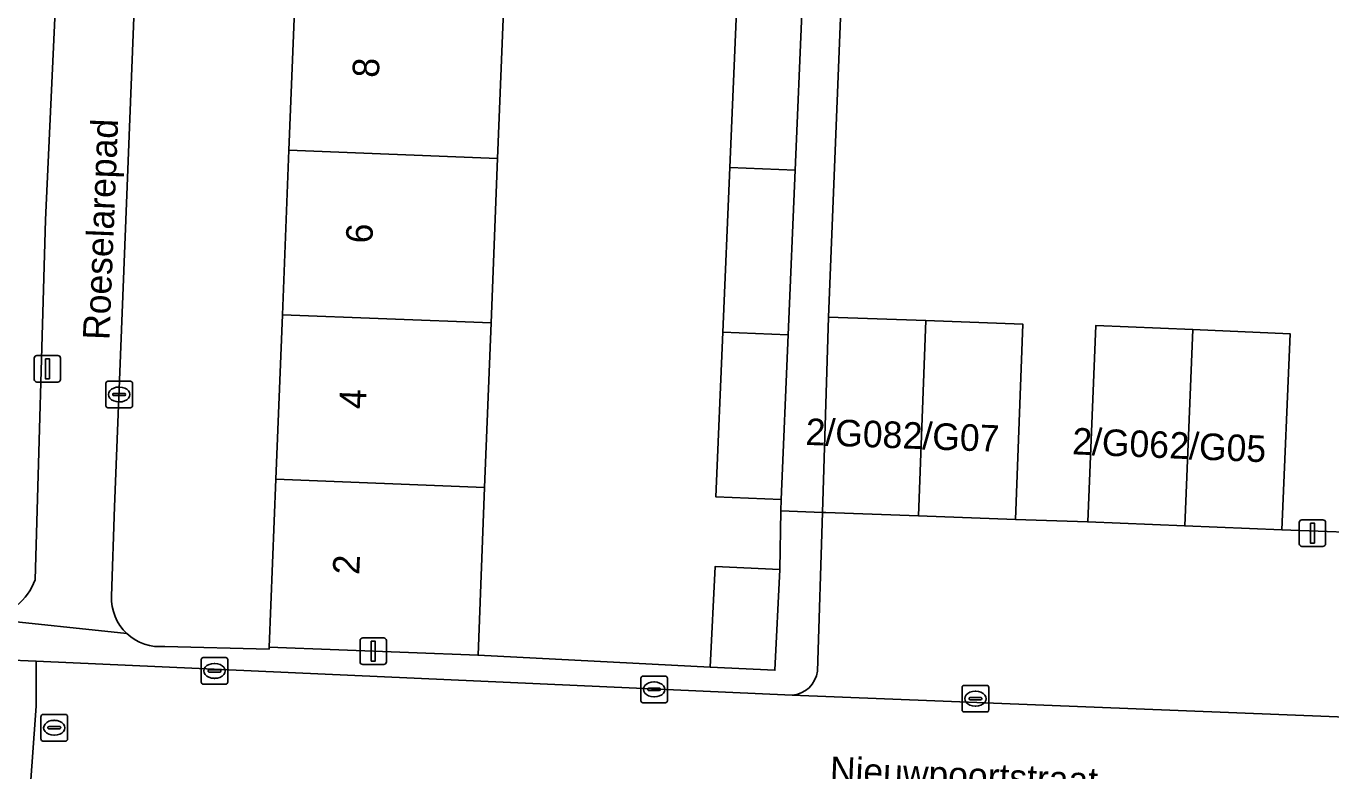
# Model space of a CAD drawing. Extents: x 160732 to 162107, y 387428 to 388479.
# Drawn here: x 161156.38 to 161205.54, y 387527.39 to 387555.43 of the extents above; entities that cross this region are included whole.
import ezdxf

# ---------------------------------------------------------------- set-up
doc = ezdxf.new("R2010")
doc.units = 0
for name, color, linetype in [('IMGEO_Erf', 7, 'Continuous'), ('IMGEO_Kolk', 7, 'Continuous'), ('IMGEO_Lichtmast', 7, 'Continuous'), ('IMGEO_Muur', 7, 'Continuous'), ('IMGEO_Openbare_ruimte_label', 7, 'Continuous'), ('IMGEO_Pand', 7, 'Continuous'), ('IMGEO_Pand_nummerreeks', 7, 'Continuous'), ('IMGEO_Parkeervlak_open', 7, 'Continuous'), ('IMGEO_Rijbaan_lokaal_open', 7, 'Continuous'), ('IMGEO_Rioolput', 7, 'Continuous'), ('IMGEO_Voetpad_open', 7, 'Continuous')]:
    doc.layers.add(name, color=color, linetype=linetype)

msp = doc.modelspace()

# ---------------------------------------------------------------- linework, layer by layer
at = {"layer": 'IMGEO_Erf'}
for points in [[(161156.715, 387534.59), (161157.113, 387548.142), (161158.354, 387575.006)], [(161161.189, 387574.824), (161159.709, 387537.335), (161159.601, 387533.972)], [(161205.924, 387560.017), (161199.746, 387560.266), (161199.575, 387556.024), (161193.395, 387556.274), (161193.566, 387560.516), (161187.266, 387560.77), (161186.614, 387544.478), (161190.269, 387544.344), (161193.924, 387544.211), (161193.655, 387536.856), (161196.373, 387536.766), (161196.679, 387544.156), (161200.34, 387544.004), (161203.998, 387543.853), (161203.692, 387536.462), (161206.427, 387536.369)], [(161161.61, 387532.081), (161165.535, 387531.976), (161165.538, 387532.053), (161165.788, 387538.37), (161166.032, 387544.565), (161166.277, 387550.76), (161166.522, 387556.956)], [(161174.387, 387556.646), (161174.142, 387550.45), (161173.897, 387544.255), (161173.653, 387538.06), (161173.403, 387531.743), (161182.155, 387531.299), (161182.34, 387535.088), (161184.775, 387534.97), (161184.818, 387537.186), (161184.826, 387537.612), (161182.362, 387537.716), (161182.624, 387543.911), (161182.887, 387550.105), (161183.15, 387556.301)]]:
    msp.add_lwpolyline(points, dxfattribs=at)
for centre, radius, start, end in [((161154.582, 387535.364), 2.27, 278.551, 340.0486), ((161161.408, 387533.882), 1.81, 177.1382, 226.7727), ((161161.413, 387533.887), 1.817, 226.7839, 276.2269)]:
    msp.add_arc(centre, radius, start, end, dxfattribs=at)
at = {"layer": 'IMGEO_Kolk'}
for p, q in [((161159.385, 387541.137), (161159.385, 387541.989)), ((161159.46, 387542.063), (161160.312, 387542.063)), ((161160.386, 387541.989), (161160.386, 387541.137)), ((161159.644, 387541.557), (161159.644, 387541.569)), ((161160.082, 387541.52), (161159.684, 387541.52)), ((161159.687, 387541.606), (161160.085, 387541.606)), ((161159.873, 387541.843), (161159.898, 387541.843)), ((161160.128, 387541.569), (161160.128, 387541.557)), ((161160.312, 387541.063), (161159.46, 387541.063)), ((161159.896, 387541.283), (161159.871, 387541.283)), ((161163.051, 387531.656), (161163.903, 387531.656)), ((161162.976, 387530.73), (161162.976, 387531.582)), ((161163.235, 387531.15), (161163.235, 387531.162)), ((161163.278, 387531.199), (161163.676, 387531.199)), ((161163.464, 387531.436), (161163.489, 387531.436)), ((161163.719, 387531.162), (161163.719, 387531.15)), ((161163.977, 387531.582), (161163.977, 387530.73)), ((161163.903, 387530.656), (161163.051, 387530.656)), ((161163.673, 387531.113), (161163.275, 387531.113)), ((161163.487, 387530.876), (161163.462, 387530.876)), ((161179.538, 387530.033), (161179.538, 387530.885)), ((161179.613, 387530.959), (161180.465, 387530.959)), ((161180.026, 387530.739), (161180.051, 387530.739)), ((161180.539, 387530.885), (161180.539, 387530.033)), ((161179.797, 387530.453), (161179.797, 387530.465)), ((161180.235, 387530.416), (161179.837, 387530.416)), ((161179.84, 387530.502), (161180.238, 387530.502)), ((161180.049, 387530.179), (161180.024, 387530.179)), ((161180.281, 387530.465), (161180.281, 387530.453)), ((161191.643, 387529.684), (161191.643, 387530.536)), ((161191.718, 387530.61), (161192.57, 387530.61)), ((161192.131, 387530.39), (161192.156, 387530.39)), ((161192.644, 387530.536), (161192.644, 387529.684)), ((161180.465, 387529.959), (161179.613, 387529.959)), ((161191.902, 387530.104), (161191.902, 387530.116)), ((161192.34, 387530.067), (161191.942, 387530.067)), ((161191.945, 387530.153), (161192.343, 387530.153)), ((161192.154, 387529.83), (161192.129, 387529.83)), ((161192.386, 387530.116), (161192.386, 387530.104)), ((161192.57, 387529.61), (161191.718, 387529.61))]:
    msp.add_line(p, q, dxfattribs=at)
for points in [[(161159.385, 387541.137), (161159.385, 387541.989)], [(161159.46, 387542.063), (161160.312, 387542.063)], [(161160.386, 387541.989), (161160.386, 387541.137)], [(161160.312, 387541.063), (161159.46, 387541.063)], [(161163.051, 387531.656), (161163.903, 387531.656)], [(161162.976, 387530.73), (161162.976, 387531.582)], [(161163.977, 387531.582), (161163.977, 387530.73)], [(161163.903, 387530.656), (161163.051, 387530.656)], [(161179.538, 387530.033), (161179.538, 387530.885)], [(161179.613, 387530.959), (161180.465, 387530.959)], [(161180.539, 387530.885), (161180.539, 387530.033)], [(161191.643, 387529.684), (161191.643, 387530.536)], [(161191.718, 387530.61), (161192.57, 387530.61)], [(161192.644, 387530.536), (161192.644, 387529.684)], [(161180.465, 387529.959), (161179.613, 387529.959)], [(161192.57, 387529.61), (161191.718, 387529.61)]]:
    msp.add_lwpolyline(points, dxfattribs=at)
for centre, radius, start, end in [((161159.462, 387541.987), 0.0765, 91.552, 178.448), ((161159.462, 387541.987), 0.0765, 91.552, 178.448), ((161160.31, 387541.987), 0.0765, 1.552, 88.448), ((161160.31, 387541.987), 0.0765, 1.552, 88.448), ((161159.684, 387541.566), 0.0403, 85.8775, 175.7526), ((161159.681, 387541.556), 0.0366, 178.938, 274.7102), ((161160.085, 387541.563), 0.043, 264.8664, 352.4533), ((161160.089, 387541.568), 0.0386, 1.7309, 96.639), ((161159.462, 387541.139), 0.0765, 181.552, 268.448), ((161159.462, 387541.139), 0.0765, 181.552, 268.448), ((161160.31, 387541.139), 0.0765, 271.552, 358.448), ((161160.31, 387541.139), 0.0765, 271.552, 358.448), ((161163.053, 387531.58), 0.0765, 91.552, 178.448), ((161163.053, 387531.58), 0.0765, 91.552, 178.448), ((161163.901, 387531.58), 0.0765, 1.552, 88.448), ((161163.901, 387531.58), 0.0765, 1.552, 88.448), ((161163.275, 387531.159), 0.0403, 85.8775, 175.7526), ((161163.272, 387531.149), 0.0366, 178.938, 274.7102), ((161163.676, 387531.156), 0.043, 264.8664, 352.4533), ((161163.68, 387531.161), 0.0386, 1.7309, 96.639), ((161163.053, 387530.732), 0.0765, 181.552, 268.448), ((161163.053, 387530.732), 0.0765, 181.552, 268.448), ((161163.901, 387530.732), 0.0765, 271.552, 358.448), ((161163.901, 387530.732), 0.0765, 271.552, 358.448), ((161179.615, 387530.883), 0.0765, 91.552, 178.448), ((161179.615, 387530.883), 0.0765, 91.552, 178.448), ((161180.463, 387530.883), 0.0765, 1.552, 88.448), ((161180.463, 387530.883), 0.0765, 1.552, 88.448), ((161179.837, 387530.462), 0.0403, 85.8775, 175.7526), ((161179.834, 387530.452), 0.0366, 178.938, 274.7102), ((161180.238, 387530.459), 0.043, 264.8664, 352.4533), ((161180.242, 387530.464), 0.0386, 1.7309, 96.639), ((161191.72, 387530.534), 0.0765, 91.552, 178.448), ((161191.72, 387530.534), 0.0765, 91.552, 178.448), ((161192.568, 387530.534), 0.0765, 1.552, 88.448), ((161192.568, 387530.534), 0.0765, 1.552, 88.448), ((161179.615, 387530.035), 0.0765, 181.552, 268.448), ((161179.615, 387530.035), 0.0765, 181.552, 268.448), ((161180.463, 387530.035), 0.0765, 271.552, 358.448), ((161180.463, 387530.035), 0.0765, 271.552, 358.448), ((161191.72, 387529.686), 0.0765, 181.552, 268.448), ((161191.72, 387529.686), 0.0765, 181.552, 268.448), ((161191.942, 387530.113), 0.0403, 85.8775, 175.7526), ((161191.939, 387530.103), 0.0366, 178.938, 274.7102), ((161192.343, 387530.11), 0.043, 264.8664, 352.4533), ((161192.347, 387530.115), 0.0386, 1.7309, 96.639), ((161192.568, 387529.686), 0.0765, 271.552, 358.448), ((161192.568, 387529.686), 0.0765, 271.552, 358.448)]:
    msp.add_arc(centre, radius, start, end, dxfattribs=at)
for centre, major_axis, ratio, start_param, end_param in [((161159.872, 387541.563), (-0.387, 0.002), 0.722429, 4.712389, 7.853982), ((161159.897, 387541.563), (-0.39, 0.002), 0.717154, 1.570796, 4.712389), ((161163.463, 387531.156), (-0.387, 0.002), 0.722429, 4.712389, 7.853982), ((161163.488, 387531.156), (-0.39, 0.002), 0.717154, 1.570796, 4.712389), ((161180.025, 387530.459), (-0.387, 0.002), 0.722429, 4.712389, 7.853982), ((161180.05, 387530.459), (-0.39, 0.002), 0.717154, 1.570796, 4.712389), ((161192.13, 387530.11), (-0.387, 0.002), 0.722429, 4.712389, 7.853982), ((161192.155, 387530.11), (-0.39, 0.002), 0.717154, 1.570796, 4.712389)]:
    msp.add_ellipse(centre, major_axis=major_axis, ratio=ratio, start_param=start_param, end_param=end_param, dxfattribs=at)
at = {"layer": 'IMGEO_Lichtmast'}
for p, q in [((161156.785, 387543.032), (161157.575, 387543.032)), ((161157.575, 387543.032), (161156.785, 387543.032)), ((161156.685, 387542.132), (161156.685, 387542.932)), ((161156.685, 387542.932), (161156.685, 387542.132)), ((161157.675, 387542.932), (161157.675, 387542.132)), ((161157.675, 387542.132), (161157.675, 387542.932)), ((161157.575, 387542.032), (161156.785, 387542.032)), ((161156.785, 387542.032), (161157.575, 387542.032)), ((161204.345, 387535.945), (161204.345, 387536.745)), ((161204.345, 387536.745), (161204.345, 387535.945)), ((161204.445, 387536.845), (161205.235, 387536.845)), ((161205.235, 387536.845), (161204.445, 387536.845)), ((161205.335, 387536.745), (161205.335, 387535.945)), ((161205.335, 387535.945), (161205.335, 387536.745)), ((161205.235, 387535.845), (161204.445, 387535.845)), ((161204.445, 387535.845), (161205.235, 387535.845)), ((161168.96, 387531.499), (161168.96, 387532.299)), ((161168.96, 387532.299), (161168.96, 387531.499)), ((161169.06, 387532.399), (161169.85, 387532.399)), ((161169.85, 387532.399), (161169.06, 387532.399)), ((161169.95, 387532.299), (161169.95, 387531.499)), ((161169.95, 387531.499), (161169.95, 387532.299)), ((161169.85, 387531.399), (161169.06, 387531.399)), ((161169.06, 387531.399), (161169.85, 387531.399))]:
    msp.add_line(p, q, dxfattribs=at)
for points in [[(161157.105, 387542.907), (161157.255, 387542.907), (161157.255, 387542.157), (161157.105, 387542.157), (161157.105, 387542.907)], [(161204.765, 387536.72), (161204.915, 387536.72), (161204.915, 387535.97), (161204.765, 387535.97), (161204.765, 387536.72)], [(161169.38, 387532.274), (161169.53, 387532.274), (161169.53, 387531.524), (161169.38, 387531.524), (161169.38, 387532.274)]]:
    msp.add_lwpolyline(points, dxfattribs=at)
for centre, start, end in [((161156.785, 387542.932), 90, 180), ((161156.785, 387542.932), 90, 180), ((161157.575, 387542.932), 0, 90), ((161157.575, 387542.932), 360, 90), ((161156.785, 387542.132), 180, 270), ((161156.785, 387542.132), 180, 270), ((161157.575, 387542.132), 270, 0), ((161157.575, 387542.132), 270, 0), ((161204.445, 387536.745), 90, 180), ((161204.445, 387536.745), 90, 180), ((161205.235, 387536.745), 0, 90), ((161205.235, 387536.745), 360, 90), ((161204.445, 387535.945), 180, 270), ((161204.445, 387535.945), 180, 270), ((161205.235, 387535.945), 270, 0), ((161205.235, 387535.945), 270, 0), ((161169.06, 387532.299), 90, 180), ((161169.06, 387532.299), 90, 180), ((161169.85, 387532.299), 0, 90), ((161169.85, 387532.299), 360, 90), ((161169.06, 387531.499), 180, 270), ((161169.06, 387531.499), 180, 270), ((161169.85, 387531.499), 270, 0), ((161169.85, 387531.499), 270, 0)]:
    msp.add_arc(centre, 0.1, start, end, dxfattribs=at)
at = {"layer": 'IMGEO_Muur'}
msp.add_lwpolyline([(161173.403, 387531.743), (161182.155, 387531.299)], dxfattribs=at)
at = {"layer": 'IMGEO_Pand'}
for points in [[(161166.522, 387556.956), (161166.277, 387550.76), (161174.142, 387550.45), (161174.387, 387556.646)], [(161185.614, 387556.203), (161183.15, 387556.301), (161182.887, 387550.105), (161185.352, 387550.008)], [(161173.897, 387544.255), (161174.142, 387550.45), (161166.277, 387550.76), (161166.032, 387544.565)], [(161185.352, 387550.008), (161182.887, 387550.105), (161182.624, 387543.911), (161185.089, 387543.814)], [(161166.032, 387544.565), (161165.788, 387538.37), (161173.653, 387538.06), (161173.897, 387544.255)], [(161186.508, 387537.117), (161190, 387536.989), (161190.269, 387544.344), (161186.614, 387544.478), (161186.385, 387537.122)], [(161193.655, 387536.856), (161193.924, 387544.211), (161190.269, 387544.344), (161190, 387536.989)], [(161200.032, 387536.614), (161200.34, 387544.004), (161196.679, 387544.156), (161196.373, 387536.766)], [(161203.692, 387536.462), (161203.998, 387543.853), (161200.34, 387544.004), (161200.032, 387536.614)], [(161185.089, 387543.814), (161182.624, 387543.911), (161182.362, 387537.716), (161184.826, 387537.612)], [(161173.403, 387531.743), (161173.653, 387538.06), (161165.788, 387538.37), (161165.538, 387532.053)], [(161184.591, 387531.181), (161184.775, 387534.97), (161182.34, 387535.088), (161182.155, 387531.299)]]:
    msp.add_lwpolyline(points, close=True, dxfattribs=at)
at = {"layer": 'IMGEO_Parkeervlak_open'}
for points in [[(161223.236, 387529.657), (161223.347, 387529.985), (161223.523, 387535.736), (161220.063, 387535.856), (161216.463, 387535.98), (161213.737, 387536.067), (161210.079, 387536.218), (161206.427, 387536.369), (161203.692, 387536.462), (161200.032, 387536.614), (161196.373, 387536.766), (161193.655, 387536.856), (161190, 387536.989), (161186.508, 387537.117), (161186.385, 387537.122), (161186.19, 387531.148)], [(161185.233, 387530.24), (161224.12, 387528.698)]]:
    msp.add_lwpolyline(points, dxfattribs=at)
msp.add_arc((161185.158, 387531.277), 1.04, 274.1375, 352.8525, dxfattribs=at)
at = {"layer": 'IMGEO_Rijbaan_lokaal_open'}
msp.add_lwpolyline([(161150.551, 387526.662), (161156.521, 387526.524), (161156.756, 387529.831), (161156.757, 387531.52), (161150.782, 387531.772)], close=True, dxfattribs=at)
msp.add_lwpolyline([(161250.799, 387527.613), (161224.12, 387528.698), (161185.233, 387530.24), (161156.757, 387531.52), (161156.756, 387529.831), (161156.521, 387526.524), (161157.05, 387526.491), (161182.151, 387525.401), (161185.563, 387525.285), (161228.389, 387523.514), (161228.548, 387523.509), (161244.661, 387522.856), (161247.682, 387522.742), (161252.229, 387522.571)], dxfattribs=at)
at = {"layer": 'IMGEO_Rioolput'}
for p, q in [((161156.939, 387528.589), (161156.939, 387529.441)), ((161157.014, 387529.515), (161157.866, 387529.515)), ((161157.427, 387529.295), (161157.452, 387529.295)), ((161157.94, 387529.441), (161157.94, 387528.589)), ((161157.198, 387529.009), (161157.198, 387529.021)), ((161157.636, 387528.972), (161157.238, 387528.972)), ((161157.241, 387529.058), (161157.639, 387529.058)), ((161157.45, 387528.735), (161157.425, 387528.735)), ((161157.682, 387529.021), (161157.682, 387529.009)), ((161157.866, 387528.515), (161157.014, 387528.515))]:
    msp.add_line(p, q, dxfattribs=at)
for points in [[(161156.939, 387528.589), (161156.939, 387529.441)], [(161157.014, 387529.515), (161157.866, 387529.515)], [(161157.94, 387529.441), (161157.94, 387528.589)], [(161157.866, 387528.515), (161157.014, 387528.515)]]:
    msp.add_lwpolyline(points, dxfattribs=at)
for centre, radius, start, end in [((161157.016, 387529.439), 0.0765, 91.552, 178.448), ((161157.016, 387529.439), 0.0765, 91.552, 178.448), ((161157.864, 387529.439), 0.0765, 1.552, 88.448), ((161157.864, 387529.439), 0.0765, 1.552, 88.448), ((161157.238, 387529.018), 0.0403, 85.8775, 175.7526), ((161157.235, 387529.008), 0.0366, 178.938, 274.7102), ((161157.639, 387529.015), 0.043, 264.8664, 352.4533), ((161157.643, 387529.02), 0.0386, 1.7309, 96.639), ((161157.016, 387528.591), 0.0765, 181.552, 268.448), ((161157.016, 387528.591), 0.0765, 181.552, 268.448), ((161157.864, 387528.591), 0.0765, 271.552, 358.448), ((161157.864, 387528.591), 0.0765, 271.552, 358.448)]:
    msp.add_arc(centre, radius, start, end, dxfattribs=at)
for centre, major_axis, ratio, start_param, end_param in [((161157.426, 387529.015), (-0.387, 0.002), 0.722429, 4.712389, 7.853982), ((161157.451, 387529.015), (-0.39, 0.002), 0.717154, 1.570796, 4.712389)]:
    msp.add_ellipse(centre, major_axis=major_axis, ratio=ratio, start_param=start_param, end_param=end_param, dxfattribs=at)
at = {"layer": 'IMGEO_Voetpad_open'}
for points in [[(161160.169, 387532.563), (161154.919, 387533.12), (161148.873, 387533.469), (161136.191, 387533.922), (161136.177, 387533.542), (161131.639, 387533.72), (161118.993, 387534.338), (161116.748, 387536.89), (161118.175, 387572.62), (161118.779, 387585.972)], [(161158.354, 387575.006), (161157.113, 387548.142), (161156.715, 387534.59)], [(161159.601, 387533.972), (161159.709, 387537.335), (161161.189, 387574.824)], [(161186.19, 387531.148), (161186.385, 387537.122), (161184.818, 387537.186), (161184.775, 387534.97), (161184.591, 387531.181), (161182.155, 387531.299), (161173.403, 387531.743), (161165.538, 387532.053), (161165.535, 387531.976), (161161.61, 387532.081)], [(161154.919, 387533.12), (161160.169, 387532.563)], [(161118.93, 387533.102), (161150.782, 387531.772), (161156.757, 387531.52), (161185.233, 387530.24)]]:
    msp.add_lwpolyline(points, dxfattribs=at)
msp.add_lwpolyline([(161187.266, 387560.77), (161187.382, 387563.65), (161187.584, 387568.645), (161187.879, 387575.683), (161186.416, 387575.744), (161186.118, 387568.643), (161185.95, 387564.742), (161185.877, 387562.397), (161185.614, 387556.203), (161185.352, 387550.008), (161185.089, 387543.814), (161184.826, 387537.612), (161184.818, 387537.186), (161186.385, 387537.122), (161186.614, 387544.478)], close=True, dxfattribs=at)
for centre, radius, start, end in [((161154.582, 387535.364), 2.27, 278.551, 340.0486), ((161161.408, 387533.882), 1.81, 177.1382, 226.7727), ((161161.413, 387533.887), 1.817, 226.7839, 276.2269), ((161185.158, 387531.277), 1.04, 274.1375, 352.8525)]:
    msp.add_arc(centre, radius, start, end, dxfattribs=at)

# ---------------------------------------------------------------- texts
at = {"layer": 'IMGEO_Openbare_ruimte_label'}
for s, rotation, p in [('Roeselarepad', 87.7071, (161159.514, 387543.603)), ('Nieuwpoortstraat', 357.6498, (161186.644, 387526.935))]:
    msp.add_text(s, height=1, rotation=rotation, dxfattribs=at).set_placement(p)
at = {"layer": 'IMGEO_Pand_nummerreeks'}
for s, rotation, p in [('8', 87.7378, (161169.667, 387553.477)), ('6', 87.7378, (161169.421, 387547.238)), ('4', 87.7378, (161169.174, 387541.002)), ('2/G08', 357.9078, (161185.733, 387539.667)), ('2/G07', 357.9086, (161189.388, 387539.534)), ('2/G06', 357.6215, (161195.776, 387539.313)), ('2/G05', 357.6215, (161199.435, 387539.161)), ('2', 87.7378, (161168.928, 387534.764))]:
    msp.add_text(s, height=1, rotation=rotation, dxfattribs=at).set_placement(p)

doc.saveas('drawing.dxf')
